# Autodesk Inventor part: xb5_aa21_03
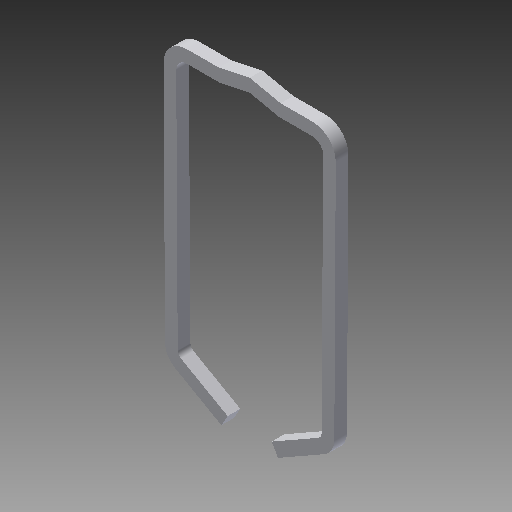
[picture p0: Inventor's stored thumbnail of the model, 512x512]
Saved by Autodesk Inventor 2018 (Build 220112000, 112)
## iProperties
Company: TraceParts S.A.
Created: 2018-05
Part Number: xb5_aa21_03
Checked By: TraceParts S.A.
Material: Generic
Catalog Web Link: www.traceparts.com
Document SubType Name: Modeling
Designer: TraceParts
Density: 1 g/cm^3
Appearance: Default
Author: TraceParts
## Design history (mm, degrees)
feature "xb5_aa21_03.ipt"
body "Solid1"
